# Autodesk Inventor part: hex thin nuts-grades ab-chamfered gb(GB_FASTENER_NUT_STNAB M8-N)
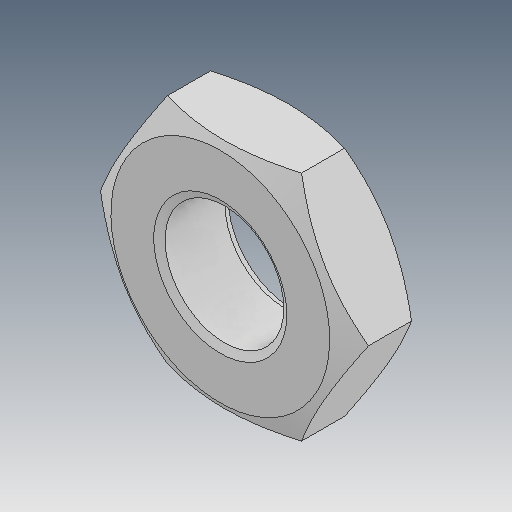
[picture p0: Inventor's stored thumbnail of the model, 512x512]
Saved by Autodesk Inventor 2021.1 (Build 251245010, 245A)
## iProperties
Created: 2019-12
Part Number: hex thin nuts-grades ab-chamfered gb(GB_FASTENER_NUT_STNAB M8-N)
Material: Ogólny
Document SubType Name: Modeling
Designer: user
Density: 1 g/cm^3
Appearance: Domyślna
Author: user
Revision Number: ÈÎºÎ
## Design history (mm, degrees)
feature "ÊäÈë1"
node "Bryła1"
